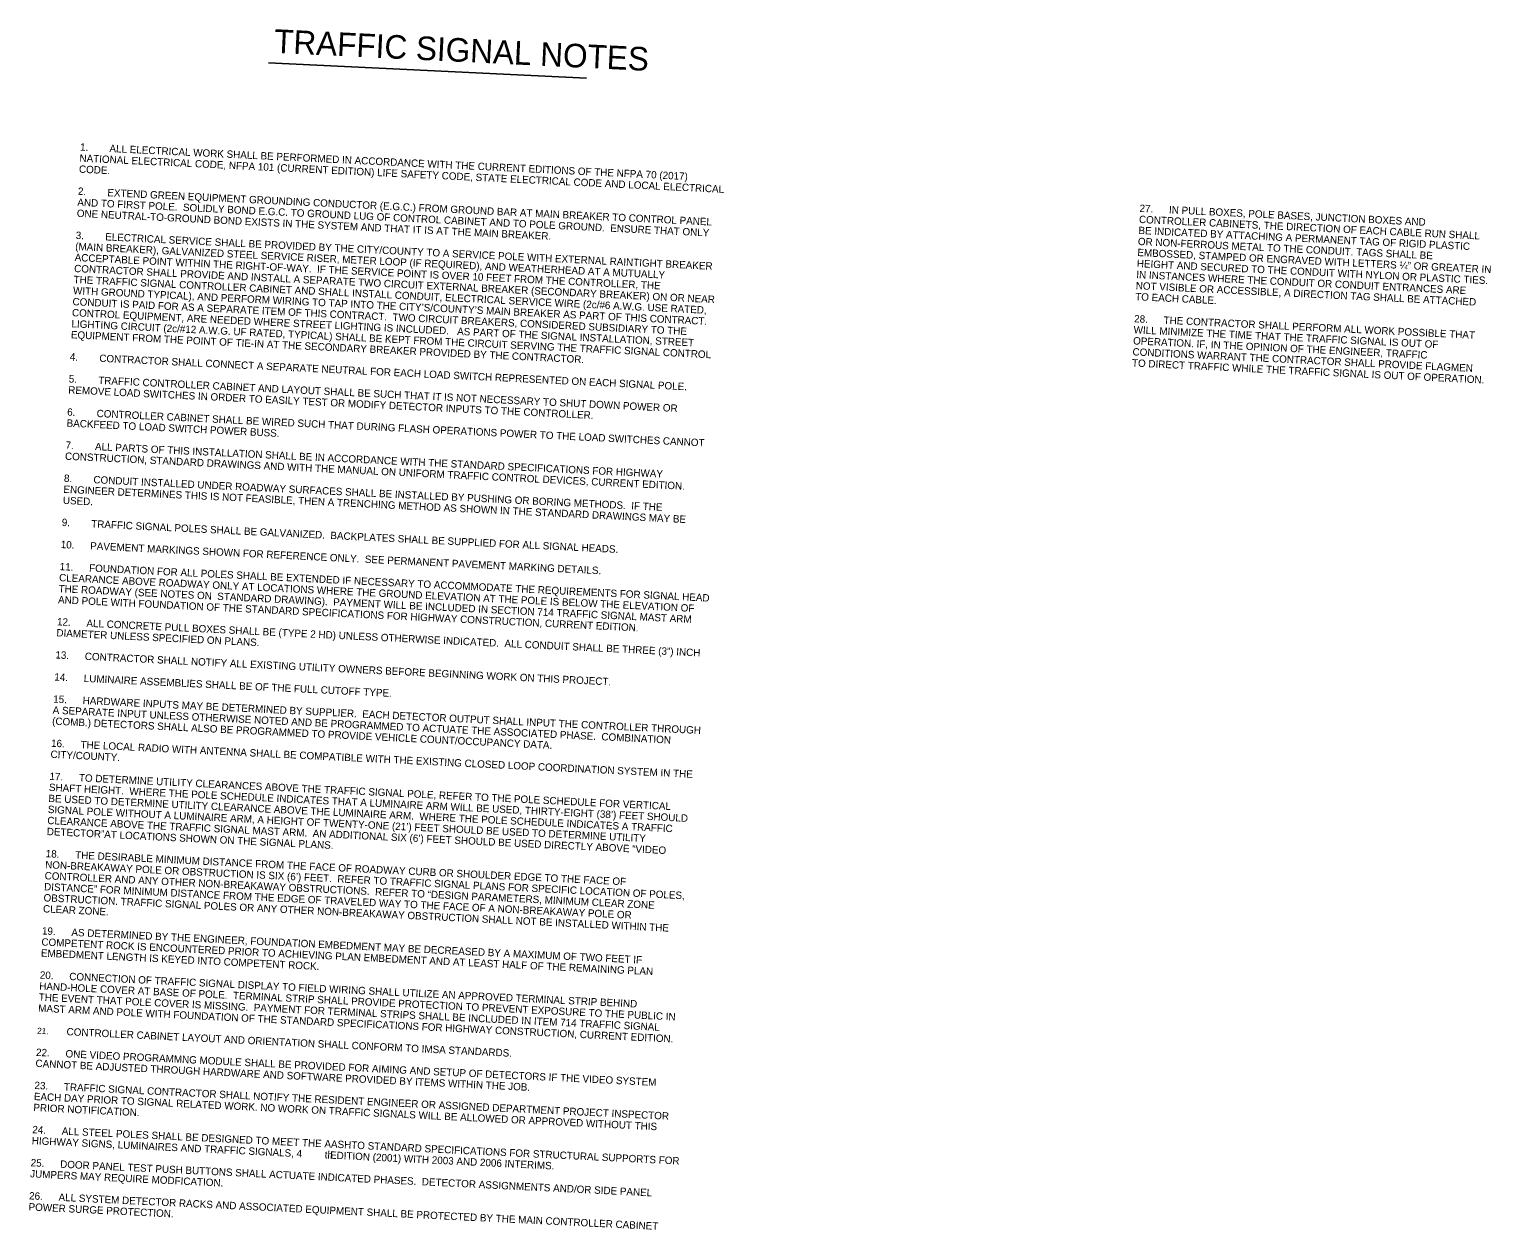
# Model space of a CAD drawing. Extents: x 660985 to 662601, y 642519 to 643065.
# Drawn here: x 660985.2 to 661480.9, y 642519.1 to 642926.4 of the extents above; entities that cross this region are included whole.
import ezdxf

# ---------------------------------------------------------------- set-up
doc = ezdxf.new("R2010")
doc.units = 0
doc.layers.add('R_Proposed Road Annot', color=7, linetype='Continuous')

msp = doc.modelspace()

# ---------------------------------------------------------------- linework, layer by layer
at = {"layer": 'R_Proposed Road Annot'}
msp.add_line((661066.36, 642915.05), (661174.22, 642909.81), dxfattribs=at)

# ---------------------------------------------------------------- texts
for s, height, p in [('TRAFFIC SIGNAL NOTES', 8, (661068.12, 642918.43)), ('1.', 2.5, (661002.41, 642885.23)), ('ALL ELECTRICAL WORK SHALL BE PERFORMED IN ACCORDANCE WITH THE CURRENT EDITIONS OF THE NFPA 70 (2017) ', 2.5, (661012.39, 642884.75)), ('NATIONAL ELECTRICAL CODE, NFPA 101 (CURRENT EDITION) LIFE SAFETY CODE, STATE ELECTRICAL CODE AND LOCAL ELECTRICAL ', 2.5, (661002.22, 642881.49)), ('CODE.', 2.5, (661002.04, 642877.74)), ('2.', 2.5, (661001.68, 642870.25)), ('EXTEND GREEN EQUIPMENT GROUNDING CONDUCTOR (E.G.C.) FROM GROUND BAR AT MAIN BREAKER TO CONTROL PANEL ', 2.5, (661011.67, 642869.76)), ('AND TO FIRST POLE.  SOLIDLY BOND E.G.C. TO GROUND LUG OF CONTROL CABINET AND TO POLE GROUND.  ENSURE THAT ONLY ', 2.5, (661001.5, 642866.5)), ('27.', 2.5, (661361.7, 642864.44)), ('IN PULL BOXES, POLE BASES, JUNCTION BOXES AND ', 2.5, (661371.69, 642863.95)), ('ONE NEUTRAL-TO-GROUND BOND EXISTS IN THE SYSTEM AND THAT IT IS AT THE MAIN BREAKER.', 2.5, (661001.32, 642862.76)), ('CONTROLLER CABINETS, THE DIRECTION OF EACH CABLE RUN SHALL ', 2.5, (661361.52, 642860.69)), ('3.', 2.5, (661000.95, 642855.27)), ('ELECTRICAL SERVICE SHALL BE PROVIDED BY THE CITY/COUNTY TO A SERVICE POLE WITH EXTERNAL RAINTIGHT BREAKER ', 2.5, (661010.94, 642854.78)), ('OR NON-FERROUS METAL TO THE CONDUIT. TAGS SHALL BE ', 2.5, (661361.15, 642853.2)), ('BE INDICATED BY ATTACHING A PERMANENT TAG OF RIGID PLASTIC ', 2.5, (661361.34, 642856.95)), ('(MAIN BREAKER), GALVANIZED STEEL SERVICE RISER, METER LOOP (IF REQUIRED), AND WEATHERHEAD AT A MUTUALLY ', 2.5, (661000.77, 642851.52)), ('EMBOSSED, STAMPED OR ENGRAVED WITH LETTERS ¼” OR GREATER IN ', 2.5, (661360.97, 642849.46)), ('ACCEPTABLE POINT WITHIN THE RIGHT-OF-WAY.  IF THE SERVICE POINT IS OVER 10 FEET FROM THE CONTROLLER, THE ', 2.5, (661000.59, 642847.78)), ('CONTRACTOR SHALL PROVIDE AND INSTALL A SEPARATE TWO CIRCUIT EXTERNAL BREAKER (SECONDARY BREAKER) ON OR NEAR ', 2.5, (661000.41, 642844.03)), ('HEIGHT AND SECURED TO THE CONDUIT WITH NYLON OR PLASTIC TIES. ', 2.5, (661360.79, 642845.71)), ('THE TRAFFIC SIGNAL CONTROLLER CABINET AND SHALL INSTALL CONDUIT, ELECTRICAL SERVICE WIRE (2c/#6 A.W.G. USE RATED, ', 2.5, (661000.22, 642840.29)), ('IN INSTANCES WHERE THE CONDUIT OR CONDUIT ENTRANCES ARE ', 2.5, (661360.61, 642841.97)), ('WITH GROUND TYPICAL), AND PERFORM WIRING TO TAP INTO THE CITY’S/COUNTY’S MAIN BREAKER AS PART OF THIS CONTRACT.  ', 2.5, (661000.04, 642836.54)), ('TO EACH CABLE.', 2.5, (661360.24, 642834.48)), ('NOT VISIBLE OR ACCESSIBLE, A DIRECTION TAG SHALL BE ATTACHED ', 2.5, (661360.43, 642838.22)), ('CONTROL EQUIPMENT, ARE NEEDED WHERE STREET LIGHTING IS INCLUDED.   AS PART OF THE SIGNAL INSTALLATION, STREET ', 2.5, (660999.68, 642829.05)), ('CONDUIT IS PAID FOR AS A SEPARATE ITEM OF THIS CONTRACT.  TWO CIRCUIT BREAKERS, CONSIDERED SUBSIDIARY TO THE ', 2.5, (660999.86, 642832.79)), ('LIGHTING CIRCUIT (2c/#12 A.W.G. UF RATED, TYPICAL) SHALL BE KEPT FROM THE CIRCUIT SERVING THE TRAFFIC SIGNAL CONTROL ', 2.5, (660999.5, 642825.3)), ('28.', 2.5, (661359.88, 642826.98)), ('THE CONTRACTOR SHALL PERFORM ALL WORK POSSIBLE THAT ', 2.5, (661369.87, 642826.5)), ('EQUIPMENT FROM THE POINT OF TIE-IN AT THE SECONDARY BREAKER PROVIDED BY THE CONTRACTOR.', 2.5, (660999.31, 642821.56)), ('OPERATION. IF, IN THE OPINION OF THE ENGINEER, TRAFFIC ', 2.5, (661359.52, 642819.49)), ('WILL MINIMIZE THE TIME THAT THE TRAFFIC SIGNAL IS OUT OF ', 2.5, (661359.7, 642823.24)), ('4.', 2.5, (660998.95, 642814.07)), ('CONTRACTOR SHALL CONNECT A SEPARATE NEUTRAL FOR EACH LOAD SWITCH REPRESENTED ON EACH SIGNAL POLE.', 2.5, (661008.94, 642813.58)), ('CONDITIONS WARRANT THE CONTRACTOR SHALL PROVIDE FLAGMEN ', 2.5, (661359.33, 642815.75)), ('TO DIRECT TRAFFIC WHILE THE TRAFFIC SIGNAL IS OUT OF OPERATION.', 2.5, (661359.15, 642812)), ('5.', 2.5, (660998.59, 642806.57)), ('TRAFFIC CONTROLLER CABINET AND LAYOUT SHALL BE SUCH THAT IT IS NOT NECESSARY TO SHUT DOWN POWER OR ', 2.5, (661008.58, 642806.09)), ('REMOVE LOAD SWITCHES IN ORDER TO EASILY TEST OR MODIFY DETECTOR INPUTS TO THE CONTROLLER.', 2.5, (660998.41, 642802.83)), ('6.', 2.5, (660998.04, 642795.34)), ('CONTROLLER CABINET SHALL BE WIRED SUCH THAT DURING FLASH OPERATIONS POWER TO THE LOAD SWITCHES CANNOT ', 2.5, (661008.03, 642794.85)), ('BACKFEED TO LOAD SWITCH POWER BUSS.', 2.5, (660997.86, 642791.59)), ('7.', 2.5, (660997.5, 642784.1)), ('CONSTRUCTION, STANDARD DRAWINGS AND WITH THE MANUAL ON UNIFORM TRAFFIC CONTROL DEVICES, CURRENT EDITION.', 2.5, (660997.31, 642780.36)), ('ALL PARTS OF THIS INSTALLATION SHALL BE IN ACCORDANCE WITH THE STANDARD SPECIFICATIONS FOR HIGHWAY ', 2.5, (661007.48, 642783.62)), ('ENGINEER DETERMINES THIS IS NOT FEASIBLE, THEN A TRENCHING METHOD AS SHOWN IN THE STANDARD DRAWINGS MAY BE ', 2.5, (660996.77, 642769.12)), ('8.', 2.5, (660996.95, 642772.86)), ('CONDUIT INSTALLED UNDER ROADWAY SURFACES SHALL BE INSTALLED BY PUSHING OR BORING METHODS.  IF THE ', 2.5, (661006.94, 642772.38)), ('USED.', 2.5, (660996.59, 642765.37)), ('9.', 2.5, (660996.22, 642757.88)), ('TRAFFIC SIGNAL POLES SHALL BE GALVANIZED.  BACKPLATES SHALL BE SUPPLIED FOR ALL SIGNAL HEADS.', 2.5, (661006.21, 642757.4)), ('10.', 2.5, (660995.86, 642750.39)), ('PAVEMENT MARKINGS SHOWN FOR REFERENCE ONLY.  SEE PERMANENT PAVEMENT MARKING DETAILS.', 2.5, (661005.85, 642749.91)), ('CLEARANCE ABOVE ROADWAY ONLY AT LOCATIONS WHERE THE GROUND ELEVATION AT THE POLE IS BELOW THE ELEVATION OF ', 2.5, (660995.31, 642739.15)), ('11.', 2.5, (660995.5, 642742.9)), ('FOUNDATION FOR ALL POLES SHALL BE EXTENDED IF NECESSARY TO ACCOMMODATE THE REQUIREMENTS FOR SIGNAL HEAD ', 2.5, (661005.48, 642742.41)), ('THE ROADWAY (SEE NOTES ON  STANDARD DRAWING).  PAYMENT WILL BE INCLUDED IN SECTION 714 TRAFFIC SIGNAL MAST ARM ', 2.5, (660995.13, 642735.41)), ('AND POLE WITH FOUNDATION OF THE STANDARD SPECIFICATIONS FOR HIGHWAY CONSTRUCTION, CURRENT EDITION.', 2.5, (660994.95, 642731.66)), ('DIAMETER UNLESS SPECIFIED ON PLANS.  ', 2.5, (660994.4, 642720.43)), ('12.', 2.5, (660994.59, 642724.17)), ('ALL CONCRETE PULL BOXES SHALL BE (TYPE 2 HD) UNLESS OTHERWISE INDICATED.  ALL CONDUIT SHALL BE THREE (3”) INCH ', 2.5, (661004.57, 642723.69)), ('13.', 2.5, (660994.04, 642712.94)), ('CONTRACTOR SHALL NOTIFY ALL EXISTING UTILITY OWNERS BEFORE BEGINNING WORK ON THIS PROJECT.', 2.5, (661004.03, 642712.45)), ('14.', 2.5, (660993.68, 642705.44)), ('LUMINAIRE ASSEMBLIES SHALL BE OF THE FULL CUTOFF TYPE.', 2.5, (661003.66, 642704.96)), ('15.', 2.5, (660993.31, 642697.95)), ('HARDWARE INPUTS MAY BE DETERMINED BY SUPPLIER.  EACH DETECTOR OUTPUT SHALL INPUT THE CONTROLLER THROUGH ', 2.5, (661003.3, 642697.47)), ('A SEPARATE INPUT UNLESS OTHERWISE NOTED AND BE PROGRAMMED TO ACTUATE THE ASSOCIATED PHASE.  COMBINATION ', 2.5, (660993.13, 642694.21)), ('(COMB.) DETECTORS SHALL ALSO BE PROGRAMMED TO PROVIDE VEHICLE COUNT/OCCUPANCY DATA.', 2.5, (660992.95, 642690.46)), ('16.', 2.5, (660992.58, 642682.97)), ('THE LOCAL RADIO WITH ANTENNA SHALL BE COMPATIBLE WITH THE EXISTING CLOSED LOOP COORDINATION SYSTEM IN THE ', 2.5, (661002.57, 642682.49)), ('CITY/COUNTY.', 2.5, (660992.4, 642679.22)), ('17.', 2.5, (660992.04, 642671.73)), ('TO DETERMINE UTILITY CLEARANCES ABOVE THE TRAFFIC SIGNAL POLE, REFER TO THE POLE SCHEDULE FOR VERTICAL ', 2.5, (661002.03, 642671.25)), ('SHAFT HEIGHT.  WHERE THE POLE SCHEDULE INDICATES THAT A LUMINAIRE ARM WILL BE USED, THIRTY-EIGHT (38’) FEET SHOULD ', 2.5, (660991.86, 642667.99)), ('SIGNAL POLE WITHOUT A LUMINAIRE ARM, A HEIGHT OF TWENTY-ONE (21’) FEET SHOULD BE USED TO DETERMINE UTILITY ', 2.5, (660991.49, 642660.5)), ('BE USED TO DETERMINE UTILITY CLEARANCE ABOVE THE LUMINAIRE ARM.  WHERE THE POLE SCHEDULE INDICATES A TRAFFIC ', 2.5, (660991.68, 642664.24)), ('CLEARANCE ABOVE THE TRAFFIC SIGNAL MAST ARM.  AN ADDITIONAL SIX (6’) FEET SHOULD BE USED DIRECTLY ABOVE “VIDEO ', 2.5, (660991.31, 642656.75)), ('DETECTOR”AT LOCATIONS SHOWN ON THE SIGNAL PLANS.  ', 2.5, (660991.13, 642653.01)), ('18.', 2.5, (660990.77, 642645.51)), ('THE DESIRABLE MINIMUM DISTANCE FROM THE FACE OF ROADWAY CURB OR SHOULDER EDGE TO THE FACE OF ', 2.5, (661000.75, 642645.03)), ('NON-BREAKAWAY POLE OR OBSTRUCTION IS SIX (6’) FEET.  REFER TO TRAFFIC SIGNAL PLANS FOR SPECIFIC LOCATION OF POLES, ', 2.5, (660990.58, 642641.77)), ('CONTROLLER AND ANY OTHER NON-BREAKAWAY OBSTRUCTIONS.  REFER TO “DESIGN PARAMETERS, MINIMUM CLEAR ZONE ', 2.5, (660990.4, 642638.02)), ('OBSTRUCTION. TRAFFIC SIGNAL POLES OR ANY OTHER NON-BREAKAWAY OBSTRUCTION SHALL NOT BE INSTALLED WITHIN THE ', 2.5, (660990.04, 642630.53)), ('DISTANCE” FOR MINIMUM DISTANCE FROM THE EDGE OF TRAVELED WAY TO THE FACE OF A NON-BREAKAWAY POLE OR ', 2.5, (660990.22, 642634.28)), ('CLEAR ZONE.', 2.5, (660989.86, 642626.79)), ('COMPETENT ROCK IS ENCOUNTERED PRIOR TO ACHIEVING PLAN EMBEDMENT AND AT LEAST HALF OF THE REMAINING PLAN ', 2.5, (660989.31, 642615.55)), ('19.', 2.5, (660989.49, 642619.3)), ('AS DETERMINED BY THE ENGINEER, FOUNDATION EMBEDMENT MAY BE DECREASED BY A MAXIMUM OF TWO FEET IF ', 2.5, (660999.48, 642618.81)), ('EMBEDMENT LENGTH IS KEYED INTO COMPETENT ROCK.  ', 2.5, (660989.13, 642611.8)), ('HAND-HOLE COVER AT BASE OF POLE.  TERMINAL STRIP SHALL PROVIDE PROTECTION TO PREVENT EXPOSURE TO THE PUBLIC IN ', 2.5, (660988.58, 642600.57)), ('20.', 2.5, (660988.77, 642604.31)), ('CONNECTION OF TRAFFIC SIGNAL DISPLAY TO FIELD WIRING SHALL UTILIZE AN APPROVED TERMINAL STRIP BEHIND ', 2.5, (660998.75, 642603.83)), ('THE EVENT THAT POLE COVER IS MISSING.  PAYMENT FOR TERMINAL STRIPS SHALL BE INCLUDED IN ITEM 714 TRAFFIC SIGNAL ', 2.5, (660988.4, 642596.82)), ('MAST ARM AND POLE WITH FOUNDATION OF THE STANDARD SPECIFICATIONS FOR HIGHWAY CONSTRUCTION, CURRENT EDITION.', 2.5, (660988.22, 642593.08)), ('21.', 2.083, (660987.86, 642585.59)), ('CONTROLLER CABINET LAYOUT AND ORIENTATION SHALL CONFORM TO IMSA STANDARDS.', 2.5, (660997.84, 642585.1)), ('22.', 2.5, (660987.49, 642578.09)), ('ONE VIDEO PROGRAMMNG MODULE SHALL BE PROVIDED FOR AIMING AND SETUP OF DETECTORS IF THE VIDEO SYSTEM ', 2.5, (660997.48, 642577.61)), ('CANNOT BE ADJUSTED THROUGH HARDWARE AND SOFTWARE PROVIDED BY ITEMS WITHIN THE JOB.', 2.5, (660987.31, 642574.35)), ('23.', 2.5, (660986.95, 642566.86)), ('TRAFFIC SIGNAL CONTRACTOR SHALL NOTIFY THE RESIDENT ENGINEER OR ASSIGNED DEPARTMENT PROJECT INSPECTOR ', 2.5, (660996.93, 642566.37)), ('EACH DAY PRIOR TO SIGNAL RELATED WORK. NO WORK ON TRAFFIC SIGNALS WILL BE ALLOWED OR APPROVED WITHOUT THIS ', 2.5, (660986.76, 642563.11)), ('PRIOR NOTIFICATION.', 2.5, (660986.58, 642559.37)), ('24.', 2.5, (660986.22, 642551.87)), ('ALL STEEL POLES SHALL BE DESIGNED TO MEET THE AASHTO STANDARD SPECIFICATIONS FOR STRUCTURAL SUPPORTS FOR ', 2.5, (660996.21, 642551.39)), ('HIGHWAY SIGNS, LUMINAIRES AND TRAFFIC SIGNALS, 4', 2.5, (660986.04, 642548.13)), ('th', 2.5, (661085.38, 642543.31)), (' EDITION (2001) WITH 2003 AND 2006 INTERIMS.', 2.5, (661086.25, 642543.26)), ('JUMPERS MAY REQUIRE MODFICATION.', 2.5, (660985.49, 642536.89)), ('25.', 2.5, (660985.67, 642540.64)), ('DOOR PANEL TEST PUSH BUTTONS SHALL ACTUATE INDICATED PHASES.  DETECTOR ASSIGNMENTS AND/OR SIDE PANEL ', 2.5, (660995.66, 642540.15)), ('26.', 2.5, (660985.13, 642529.4)), ('ALL SYSTEM DETECTOR RACKS AND ASSOCIATED EQUIPMENT SHALL BE PROTECTED BY THE MAIN CONTROLLER CABINET ', 2.5, (660995.12, 642528.92)), ('POWER SURGE PROTECTION.', 2.5, (660984.95, 642525.66))]:
    msp.add_text(s, height=height, rotation=357.2199, dxfattribs=at).set_placement(p)

doc.saveas('drawing.dxf')
